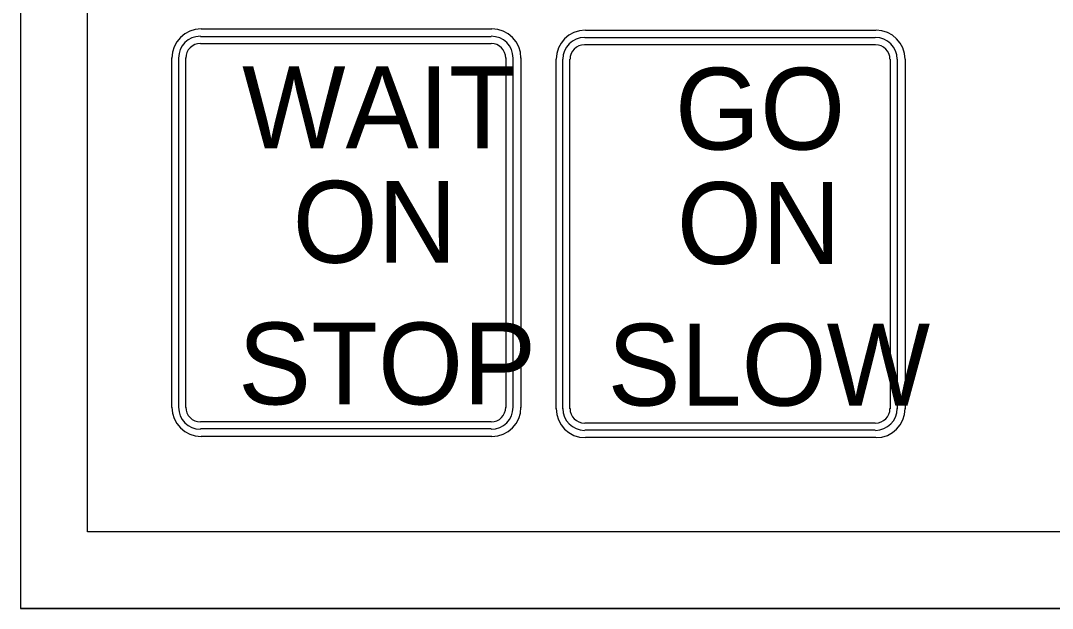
# Model space of a CAD drawing. Extents: x 21.7 to 29.1, y 5.9 to 16.2.
# Drawn here: x 25.804 to 26.612, y 13.017 to 13.478 of the extents above; entities that cross this region are included whole.
import ezdxf

# ---------------------------------------------------------------- set-up
doc = ezdxf.new("R2010")
doc.units = 0
doc.layers.add('DETL-LINE', color=7, linetype='Continuous')
doc.layers.add('USER-BORD', color=7, linetype='Continuous')

msp = doc.modelspace()

# ---------------------------------------------------------------- linework, layer by layer
at = {"layer": 'DETL-LINE'}
for points in [[(25.80407, 13.01689), (28.97928, 13.01689), (28.97928, 14.33286), (25.80407, 14.33286)], [(28.97321, 14.14685), (25.80407, 14.14685), (25.80407, 13.01694), (28.97321, 13.01694)], [(25.85652, 14.08137), (27.25819, 14.08137), (27.25819, 13.07685), (25.85652, 13.07685)]]:
    msp.add_lwpolyline(points, close=True, dxfattribs=at)
at = {"layer": 'USER-BORD'}
for p, q in [((25.94555, 13.47098), (26.173, 13.47098)), ((25.94505, 13.46515), (26.17249, 13.46515)), ((26.24594, 13.46419), (26.47339, 13.46419)), ((26.24645, 13.47002), (26.4739, 13.47002)), ((25.94505, 13.45968), (26.17249, 13.45968)), ((26.24594, 13.45872), (26.47339, 13.45872)), ((25.92259, 13.17428), (25.92259, 13.44838)), ((25.92791, 13.17428), (25.92791, 13.44838)), ((25.93338, 13.17428), (25.93338, 13.44838)), ((26.18416, 13.44838), (26.18416, 13.17428)), ((26.18962, 13.44838), (26.18962, 13.17428)), ((26.19597, 13.44838), (26.19597, 13.17428)), ((26.22349, 13.17332), (26.22349, 13.44742)), ((26.22881, 13.17332), (26.22881, 13.44742)), ((26.23428, 13.17332), (26.23428, 13.44742)), ((26.48505, 13.44742), (26.48505, 13.17332)), ((26.49052, 13.44742), (26.49052, 13.17332)), ((26.49686, 13.44742), (26.49686, 13.17332)), ((26.17249, 13.16298), (25.94505, 13.16298)), ((26.17249, 13.15751), (25.94505, 13.15751)), ((26.47339, 13.16202), (26.24594, 13.16202)), ((26.47339, 13.15655), (26.24594, 13.15655)), ((26.173, 13.15168), (25.94555, 13.15168)), ((26.4739, 13.15072), (26.24645, 13.15072))]:
    msp.add_line(p, q, dxfattribs=at)
for centre, radius, start, end in [((25.94537, 13.4482), 0.02278, 90, 180), ((26.17318, 13.4482), 0.02278, 0, 90), ((25.94486, 13.4482), 0.01709, 90, 180), ((26.17268, 13.4482), 0.01709, 0, 90), ((26.24627, 13.44724), 0.02278, 90, 180), ((26.24576, 13.44724), 0.01709, 90, 180), ((26.47357, 13.44724), 0.01709, 0, 90), ((26.47408, 13.44724), 0.02278, 0, 90), ((25.94486, 13.4482), 0.01139, 90, 180), ((26.17268, 13.4482), 0.01139, 0, 90), ((26.24576, 13.44724), 0.01139, 90, 180), ((26.47357, 13.44724), 0.01139, 0, 90), ((25.94537, 13.17446), 0.02278, 180, 270), ((25.94486, 13.17446), 0.01709, 180, 270), ((25.94486, 13.17446), 0.01139, 180, 270), ((26.17268, 13.17446), 0.01709, 270, 0), ((26.17268, 13.17446), 0.01139, 270, 0), ((26.17318, 13.17446), 0.02278, 270, 0), ((26.24627, 13.1735), 0.02278, 180, 270), ((26.24576, 13.1735), 0.01709, 180, 270), ((26.24576, 13.1735), 0.01139, 180, 270), ((26.47357, 13.1735), 0.01709, 270, 0), ((26.47357, 13.1735), 0.01139, 270, 0), ((26.47408, 13.1735), 0.02278, 270, 0)]:
    msp.add_arc(centre, radius, start, end, dxfattribs=at)

# ---------------------------------------------------------------- texts
for s, p in [('WAIT', (25.97757, 13.37744)), ('GO', (26.31649, 13.37647)), ('ON', (26.0171, 13.28777)), ('ON', (26.31799, 13.28681)), ('STOP', (25.97433, 13.17675)), ('SLOW', (26.26375, 13.17579))]:
    msp.add_text(s, height=0.064153, dxfattribs=at).set_placement(p)

doc.saveas('drawing.dxf')
